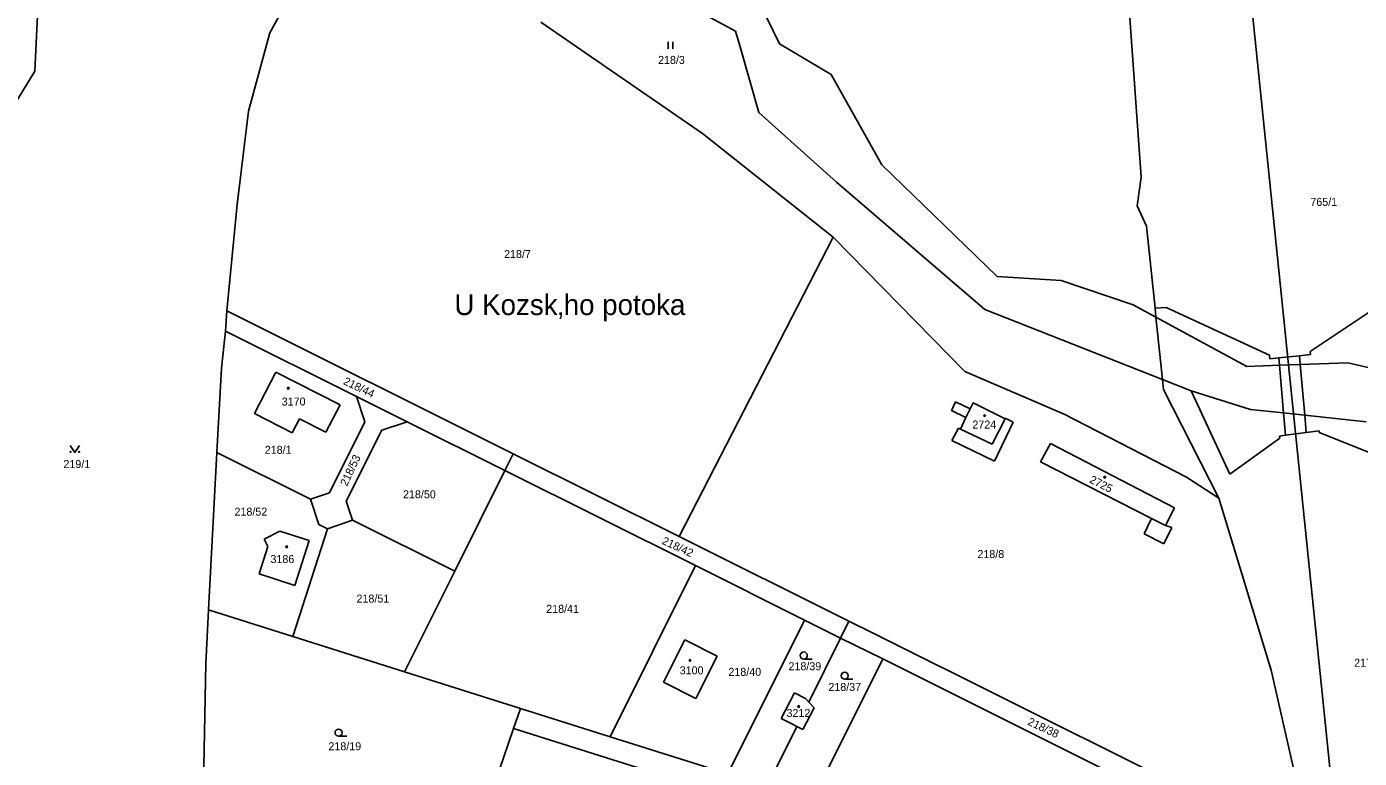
# Model space of a CAD drawing. Extents: x -735249 to -729401, y -1124843 to -1121828.
# Drawn here: x -733806.2 to -733523, y -1123120 to -1122964.5 of the extents above; entities that cross this region are included whole.
import ezdxf

# ---------------------------------------------------------------- set-up
doc = ezdxf.new("R2010")
doc.units = 0
for name, color, linetype in [('Vrstva 1', 7, 'Continuous'), ('Vrstva 10', 7, 'Continuous'), ('Vrstva 15', 7, 'Continuous'), ('Vrstva 16', 7, 'Continuous'), ('Vrstva 18', 7, 'Continuous'), ('Vrstva 19', 7, 'Continuous'), ('Vrstva 25', 7, 'Continuous'), ('Vrstva 4', 7, 'Continuous')]:
    doc.layers.add(name, color=color, linetype=linetype)

msp = doc.modelspace()

# ---------------------------------------------------------------- linework, layer by layer
at = {"layer": 'Vrstva 1'}
for points in [[(-733739.01, -1122937.63), (-733754.49, -1122965.85)], [(-733573.32, -1122940.69), (-733569.37, -1122996.52)], [(-733653.1, -1122953.96), (-733646.23, -1122968.17)], [(-733803.6, -1122956.15), (-733804.42, -1122973.98)], [(-733655.54, -1122965.49), (-733666.05, -1122959.79)], [(-733696.92, -1122963.53), (-733662.58, -1122987.23)], [(-733754.49, -1122965.85), (-733758.99, -1122982.48)], [(-733654.59, -1122968.83), (-733655.54, -1122965.49)], [(-733650.59, -1122982.72), (-733654.59, -1122968.83)], [(-733646.23, -1122968.17), (-733635.26, -1122974.65)], [(-733804.42, -1122973.98), (-733833.51, -1123021.57)], [(-733635.26, -1122974.65), (-733624.49, -1122993.91)], [(-733758.99, -1122982.48), (-733761.41, -1123002.33)], [(-733650.59, -1122982.72), (-733634.1, -1122997.54)], [(-733662.58, -1122987.23), (-733634.83, -1123009.25)], [(-733624.49, -1122993.91), (-733599.98, -1123017.6)], [(-733634.1, -1122997.54), (-733602.6, -1123024.61)], [(-733569.37, -1122996.52), (-733570.19, -1123002.6)], [(-733761.41, -1123002.33), (-733763.6, -1123024.9)], [(-733570.19, -1123002.6), (-733568.25, -1123006.91)], [(-733634.83, -1123009.25), (-733667.5, -1123072.86)], [(-733634.83, -1123009.25), (-733606.81, -1123037.79)], [(-733568.25, -1123006.91), (-733566.43, -1123024.37)], [(-733599.98, -1123017.6), (-733586.39, -1123018.47)], [(-733586.39, -1123018.47), (-733571.05, -1123023.65)], [(-733763.6, -1123024.9), (-733763.93, -1123029.23)], [(-733702.76, -1123055.26), (-733763.6, -1123024.9)], [(-733602.6, -1123024.61), (-733564.85, -1123039.49)], [(-733571.05, -1123023.65), (-733566.23, -1123026.26)], [(-733566.43, -1123024.37), (-733566.23, -1123026.26)], [(-733564.85, -1123039.49), (-733566.23, -1123026.26)], [(-733763.93, -1123029.23), (-733764.76, -1123037.11)], [(-733763.93, -1123029.23), (-733736.06, -1123043.13)], [(-733764.76, -1123037.11), (-733765.72, -1123055.03)], [(-733757.78, -1123046.75), (-733753.18, -1123037.91)], [(-733753.18, -1123037.91), (-733739.55, -1123044.86)], [(-733606.81, -1123037.79), (-733585.73, -1123046.88)], [(-733564.63, -1123041.63), (-733564.85, -1123039.49)], [(-733736.06, -1123043.13), (-733725.34, -1123048.48)], [(-733734.28, -1123048.49), (-733736.06, -1123043.13)], [(-733564.63, -1123041.63), (-733552.84, -1123064.69)], [(-733739.55, -1123044.86), (-733742.59, -1123050.71)], [(-733608.8, -1123044.27), (-733609.68, -1123046.11)], [(-733609.68, -1123046.11), (-733606.59, -1123047.58)], [(-733605.71, -1123045.74), (-733608.8, -1123044.27)], [(-733605.08, -1123044.42), (-733605.71, -1123045.74)], [(-733598.3, -1123047.82), (-733605.08, -1123044.42)], [(-733749.75, -1123050.85), (-733757.78, -1123046.75)], [(-733748.22, -1123047.85), (-733749.75, -1123050.85)], [(-733742.59, -1123050.71), (-733748.22, -1123047.85)], [(-733741.82, -1123063.6), (-733734.28, -1123048.49)], [(-733725.34, -1123048.48), (-733730.7, -1123050.28)], [(-733725.34, -1123048.48), (-733704.55, -1123058.85)], [(-733606.59, -1123047.58), (-733607.77, -1123050.05)], [(-733600.54, -1123056.86), (-733596.58, -1123048.59)], [(-733598.26, -1123047.73), (-733598.3, -1123047.82)], [(-733596.58, -1123048.59), (-733598.26, -1123047.73)], [(-733585.73, -1123046.88), (-733559.75, -1123060.22)], [(-733730.7, -1123050.28), (-733738.25, -1123065.38)], [(-733608.2, -1123049.81), (-733609.57, -1123052.47)], [(-733607.77, -1123050.05), (-733608.2, -1123049.81)], [(-733609.57, -1123052.47), (-733600.54, -1123056.86)], [(-733590.77, -1123056.96), (-733588.66, -1123053.06)], [(-733588.66, -1123053.06), (-733562.29, -1123066.75)], [(-733765.72, -1123055.03), (-733767.51, -1123088.47)], [(-733765.72, -1123055.03), (-733745.85, -1123064.94)], [(-733702.76, -1123055.26), (-733704.55, -1123058.85)], [(-733667.5, -1123072.86), (-733702.76, -1123055.26)], [(-733567.16, -1123069.04), (-733590.77, -1123056.96)], [(-733715.21, -1123080.22), (-733704.55, -1123058.85)], [(-733704.55, -1123058.85), (-733664.07, -1123079.04)], [(-733559.75, -1123060.22), (-733552.84, -1123064.69)], [(-733745.85, -1123064.94), (-733741.82, -1123063.6)], [(-733744.08, -1123070.31), (-733745.85, -1123064.94)], [(-733738.25, -1123065.38), (-733736.91, -1123069.4)], [(-733552.84, -1123064.69), (-733541.73, -1123101.29)], [(-733562.29, -1123066.75), (-733564.21, -1123070.55)], [(-733742.27, -1123071.2), (-733749.6, -1123094.12)], [(-733744.08, -1123070.31), (-733742.27, -1123071.2)], [(-733736.91, -1123069.4), (-733742.27, -1123071.2)], [(-733736.91, -1123069.4), (-733715.21, -1123080.22)], [(-733568.76, -1123072.31), (-733567.16, -1123069.04)], [(-733562.85, -1123070.95), (-733564.58, -1123074.41)], [(-733564.21, -1123070.55), (-733562.85, -1123070.95)], [(-733755.72, -1123073.45), (-733752.34, -1123071.71)], [(-733754.94, -1123074.98), (-733755.72, -1123073.45)], [(-733752.34, -1123071.71), (-733746.16, -1123073.69)], [(-733746.16, -1123073.69), (-733749.15, -1123083.24)], [(-733631.45, -1123090.85), (-733667.5, -1123072.86)], [(-733564.58, -1123074.41), (-733568.76, -1123072.31)], [(-733756.78, -1123080.76), (-733754.94, -1123074.98)], [(-733682.21, -1123115.4), (-733664.07, -1123079.04)], [(-733664.07, -1123079.04), (-733640.87, -1123090.61)], [(-733749.15, -1123083.24), (-733756.78, -1123080.76)], [(-733725.88, -1123101.61), (-733715.21, -1123080.22)], [(-733767.51, -1123088.47), (-733768.12, -1123099.89)], [(-733767.51, -1123088.47), (-733749.6, -1123094.12)], [(-733640.87, -1123090.61), (-733657.18, -1123123.3)], [(-733633.22, -1123094.43), (-733640.87, -1123090.61)], [(-733631.45, -1123090.85), (-733633.22, -1123094.43)], [(-733626.29, -1123093.42), (-733631.45, -1123090.85)], [(-733749.6, -1123094.12), (-733725.88, -1123101.61)], [(-733537.74, -1123137.59), (-733626.29, -1123093.42)], [(-733670.84, -1123103.83), (-733666.3, -1123094.81)], [(-733666.3, -1123094.81), (-733659.44, -1123098.26)], [(-733639.98, -1123108.06), (-733633.22, -1123094.43)], [(-733633.22, -1123094.43), (-733624.28, -1123098.89)], [(-733768.12, -1123099.89), (-733768.76, -1123136.23)], [(-733659.44, -1123098.26), (-733663.97, -1123107.3)], [(-733624.28, -1123098.89), (-733639.27, -1123128.96)], [(-733624.28, -1123098.89), (-733575.36, -1123123.29)], [(-733701.26, -1123109.39), (-733725.88, -1123101.61)], [(-733541.73, -1123101.29), (-733533.03, -1123139.56)], [(-733663.97, -1123107.3), (-733670.84, -1123103.83)], [(-733642.99, -1123106.07), (-733645.85, -1123111.5)], [(-733642.99, -1123106.07), (-733640.72, -1123107.26)], [(-733640.72, -1123107.26), (-733639.98, -1123108.06)], [(-733639.98, -1123108.06), (-733638.86, -1123109.27)], [(-733702.72, -1123113.66), (-733701.26, -1123109.39)], [(-733682.21, -1123115.4), (-733701.26, -1123109.39)], [(-733638.86, -1123109.27), (-733641.25, -1123113.9)], [(-733713.01, -1123143.76), (-733702.72, -1123113.66)], [(-733702.72, -1123113.66), (-733666.09, -1123125.22)], [(-733648.85, -1123125.93), (-733642.55, -1123113.22)], [(-733645.85, -1123111.5), (-733643.57, -1123112.69)], [(-733643.57, -1123112.69), (-733642.55, -1123113.22)], [(-733642.55, -1123113.22), (-733641.25, -1123113.9)], [(-733657.18, -1123123.3), (-733682.21, -1123115.4)]]:
    msp.add_lwpolyline(points, dxfattribs=at)
at = {"layer": 'Vrstva 10'}
msp.add_lwpolyline([(-733554.55, -1122875.4), (-733527.93, -1123135.14), (-733525.72, -1123160.85), (-733524.03, -1123186.32), (-733523.36, -1123211.8), (-733523.33, -1123236.18), (-733524.81, -1123261.05), (-733527.46, -1123286.21), (-733536.18, -1123335), (-733548.72, -1123382.9), (-733557.6, -1123406.95), (-733565.8, -1123430.03), (-733599.27, -1123511.46), (-733632.77, -1123591.76), (-733662.7, -1123662.58), (-733683.9, -1123713.51), (-733745.65, -1123859.1)], dxfattribs=at)
at = {"layer": 'Vrstva 25'}
for points in [[(-733669.897, -1122969.205), (-733669.897, -1122967.705)], [(-733668.863, -1122969.205), (-733668.863, -1122967.705)], [(-733796.93, -1123053.5), (-733795.93, -1123055), (-733794.93, -1123053.5)], [(-733641.05, -1123098.9), (-733639.3, -1123098.9)], [(-733632.35, -1123103.19), (-733630.6, -1123103.19)], [(-733739.89, -1123115.3), (-733738.14, -1123115.3)]]:
    msp.add_lwpolyline(points, dxfattribs=at)
for centre, radius in [((-733750.58, -1123041.34), 0.175), ((-733602.63, -1123047.18), 0.175), ((-733796.83, -1123054.9), 0.1), ((-733795.03, -1123054.9), 0.1), ((-733577.1, -1123060.26), 0.175), ((-733750.93, -1123075.04), 0.175), ((-733665.23, -1123099.16), 0.175), ((-733641.05, -1123098.15), 0.75), ((-733632.35, -1123102.44), 0.75), ((-733642.15, -1123108.99), 0.175), ((-733739.89, -1123114.55), 0.75)]:
    msp.add_circle(centre, radius, dxfattribs=at)
at = {"layer": 'Vrstva 4'}
for points in [[(-733533.44, -1123033.51), (-733516.23, -1123022.04)], [(-733564.09, -1123024.19), (-733566.43, -1123024.37)], [(-733546.95, -1123036.71), (-733566.23, -1123026.26)], [(-733564.09, -1123024.19), (-733542.12, -1123034.35)], [(-733542.12, -1123034.35), (-733542.02, -1123035.13)], [(-733540.12, -1123034.92), (-733535.73, -1123034.45)], [(-733535.73, -1123034.45), (-733533.39, -1123034.2)], [(-733535.73, -1123034.45), (-733535.57, -1123036.29)], [(-733533.39, -1123034.2), (-733533.44, -1123033.51)], [(-733546.95, -1123036.71), (-733539.99, -1123036.45)], [(-733542.02, -1123035.13), (-733540.12, -1123034.92)], [(-733540.12, -1123034.92), (-733539.99, -1123036.45)], [(-733539.99, -1123036.45), (-733535.57, -1123036.29)], [(-733539.99, -1123036.45), (-733539.1, -1123046.6)], [(-733535.57, -1123036.29), (-733525.5, -1123035.92)], [(-733535.57, -1123036.29), (-733534.62, -1123047.07)], [(-733525.5, -1123035.92), (-733511.05, -1123039.26)], [(-733564.85, -1123039.49), (-733558.77, -1123041.89)], [(-733550.52, -1123059.61), (-733558.77, -1123041.89)], [(-733546.18, -1123045.85), (-733558.77, -1123041.89)], [(-733605.71, -1123045.74), (-733606.59, -1123047.58)], [(-733539.1, -1123046.6), (-733546.18, -1123045.85)], [(-733598.3, -1123047.82), (-733601.05, -1123053.27)], [(-733539.1, -1123046.6), (-733538.69, -1123051.34)], [(-733534.62, -1123047.07), (-733539.1, -1123046.6)], [(-733534.62, -1123047.07), (-733534.3, -1123050.78)], [(-733521.54, -1123048.46), (-733534.62, -1123047.07)], [(-733601.05, -1123053.27), (-733607.77, -1123050.05)], [(-733538.69, -1123051.34), (-733539.97, -1123051.51)], [(-733539.97, -1123051.51), (-733539.92, -1123051.95)], [(-733534.3, -1123050.78), (-733538.69, -1123051.34)], [(-733531.59, -1123050.43), (-733534.3, -1123050.78)], [(-733531.53, -1123050.79), (-733531.59, -1123050.43)], [(-733520.39, -1123055.2), (-733531.53, -1123050.79)], [(-733539.92, -1123051.95), (-733550.52, -1123059.61)], [(-733567.16, -1123069.04), (-733564.21, -1123070.55)]]:
    msp.add_lwpolyline(points, dxfattribs=at)

# ---------------------------------------------------------------- texts
at = {"layer": 'Vrstva 15'}
msp.add_text('U Kozsk‚ho potoka', height=4.39998, dxfattribs=at).set_placement((-733715.27, -1123025.8))
at = {"layer": 'Vrstva 16'}
for s, p in [('765/1', (-733533.428, -1123002.6)), ('217/137', (-733524.127, -1123100.54))]:
    msp.add_text(s, height=1.7, dxfattribs=at).set_placement(p)
at = {"layer": 'Vrstva 18'}
for s, p in [('218/3', (-733672.01, -1122972.43)), ('218/7', (-733704.72, -1123013.68)), ('218/1', (-733755.57, -1123055.29)), ('219/1', (-733798.34, -1123058.31)), ('218/50', (-733726.19, -1123064.74)), ('218/52', (-733761.99, -1123068.43)), ('218/8', (-733604.16, -1123077.44)), ('218/51', (-733736.07, -1123086.9)), ('218/41', (-733695.77, -1123089.08)), ('218/39', (-733644.3, -1123101.28)), ('218/40', (-733657.06, -1123102.47)), ('218/37', (-733635.82, -1123105.68)), ('218/19', (-733742.04, -1123118.28))]:
    msp.add_text(s, height=1.7, dxfattribs=at).set_placement(p)
for s, rotation, p in [('218/44', 334.40266, (-733739.024, -1123040.427)), ('218/53', 64.60051, (-733738.114, -1123062.284)), ('218/42', 335.10266, (-733671.335, -1123074.363)), ('218/38', 334.90266, (-733593.645, -1123112.784))]:
    msp.add_text(s, height=1.7, rotation=rotation, dxfattribs=at).set_placement(p)
at = {"layer": 'Vrstva 19'}
for s, p in [('3170', (-733751.963, -1123045.03)), ('2724', (-733605.23, -1123049.91)), ('3186', (-733754.353, -1123078.5)), ('3100', (-733667.41, -1123102.15)), ('3212', (-733644.72, -1123111.22))]:
    msp.add_text(s, height=1.7, dxfattribs=at).set_placement(p)
msp.add_text('2725', height=1.7, rotation=333.00265, dxfattribs=at).set_placement((-733580.502, -1123061.313))

doc.saveas('drawing.dxf')
